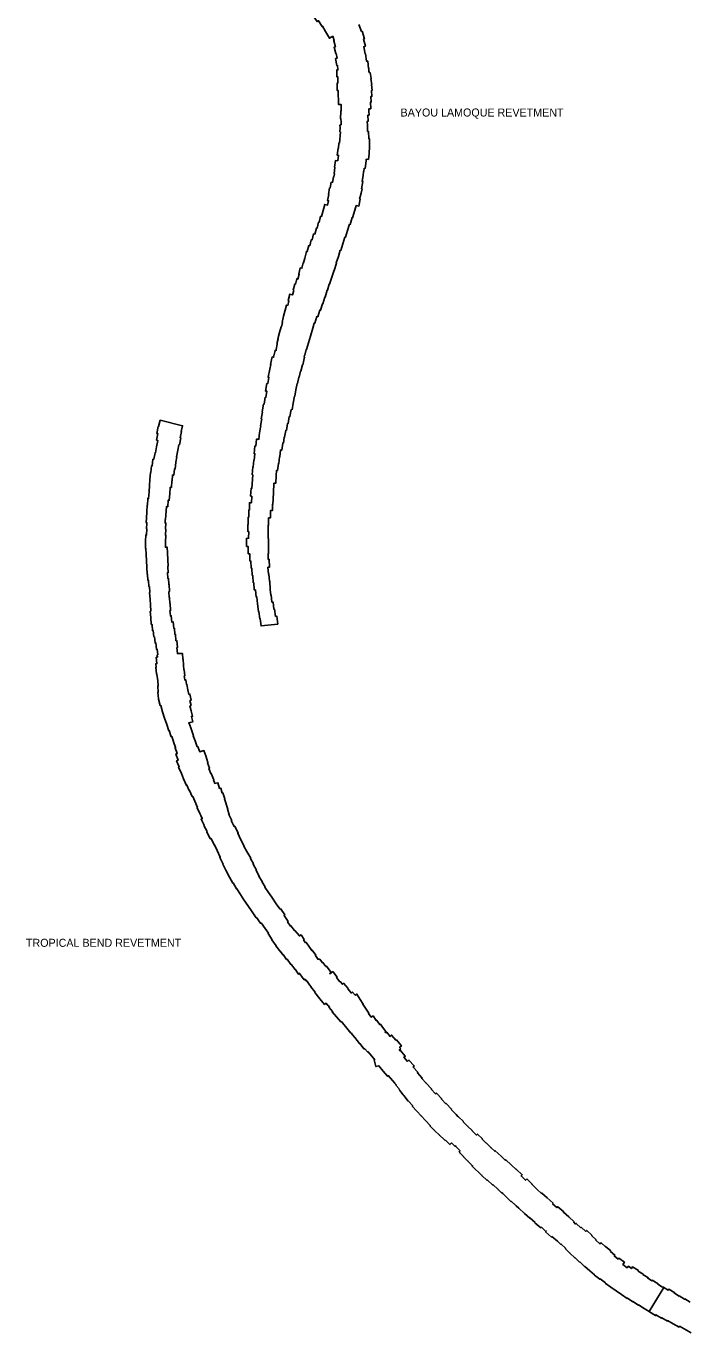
# Model space of a CAD drawing. Extents: x 2650582 to 3923188, y 277893 to 989177.
# Drawn here: x 3827116 to 3840315, y 322407 to 348533 of the extents above; entities that cross this region are included whole.
import ezdxf

# ---------------------------------------------------------------- set-up
doc = ezdxf.new("R2010")
doc.units = 0
doc.layers.add('Level 18', color=7, linetype='Continuous')
doc.layers.add('Level 3', color=7, linetype='Continuous')

msp = doc.modelspace()

# ---------------------------------------------------------------- linework, layer by layer
at = {"layer": 'Level 18'}
msp.add_lwpolyline([(3830237, 335992), (3830137, 335987)], dxfattribs=at)
at = {"layer": 'Level 3'}
for points in [[(3833239, 348329), (3833174, 348290), (3833094, 348424), (3833098, 348427), (3833037, 348530), (3833028, 348525), (3832956, 348642), (3832928, 348624), (3832849, 348742), (3832823, 348726), (3832739, 348856), (3832767, 348874), (3832711, 348962), (3832688, 348945), (3832596, 349073), (3832625, 349094)], [(3833765, 348565), (3833817, 348428), (3833825, 348431), (3833874, 348280), (3833855, 348273), (3833893, 348131), (3833861, 348122), (3833891, 347980), (3833893, 347980), (3833916, 347831), (3833941, 347833), (3833956, 347688), (3833962, 347689), (3833964, 347633), (3833972, 347602), (3833986, 347604), (3834009, 347483), (3834002, 347481), (3834021, 347365), (3834013, 347363), (3834025, 347246), (3834014, 347245), (3834023, 347127), (3834003, 347126), (3834010, 347017), (3833996, 347016), (3834001, 346882), (3833964, 346880), (3833964, 346832), (3833967, 346755), (3833943, 346755), (3833947, 346630), (3833931, 346629), (3833934, 346554), (3833935, 346427)], [(3833411, 346559), (3833410, 346611), (3833406, 346611), (3833403, 346680), (3833397, 346680), (3833400, 346835), (3833408, 346835), (3833409, 346965), (3833356, 346964), (3833351, 347245), (3833330, 347245), (3833331, 347398), (3833343, 347399), (3833343, 347516), (3833325, 347516), (3833319, 347657), (3833343, 347658), (3833333, 347750), (3833320, 347749), (3833298, 347885), (3833327, 347891), (3833307, 347989), (3833300, 347988), (3833267, 348112), (3833295, 348122), (3833259, 348241), (3833270, 348246), (3833239, 348329)], [(3833935, 346427), (3833952, 346427), (3833960, 346282), (3833973, 346281), (3833973, 346135), (3833978, 346134), (3833969, 345980), (3833968, 345980), (3833952, 345867), (3833908, 345873), (3833905, 345842), (3833910, 345841), (3833887, 345688), (3833869, 345690), (3833860, 345627), (3833858, 345628), (3833846, 345548), (3833827, 345430), (3833839, 345427), (3833817, 345281), (3833826, 345280), (3833807, 345195), (3833810, 345193), (3833776, 345074), (3833787, 345072), (3833762, 344934), (3833710, 344944), (3833683, 344855), (3833634, 344703), (3833631, 344704), (3833589, 344570), (3833576, 344573), (3833537, 344447), (3833534, 344448), (3833494, 344313), (3833484, 344315), (3833442, 344181), (3833440, 344181), (3833401, 344049), (3833391, 344051), (3833353, 343926), (3833310, 343798), (3833315, 343796), (3833272, 343650), (3833266, 343651)], [(3833267, 345585), (3833285, 345708), (3833278, 345710), (3833298, 345848), (3833339, 345842), (3833354, 345951), (3833328, 345955), (3833347, 346093), (3833354, 346093), (3833363, 346194), (3833374, 346194), (3833394, 346419), (3833383, 346420), (3833387, 346506), (3833384, 346554), (3833390, 346554), (3833390, 346560), (3833411, 346559)], [(3832107, 342044), (3832113, 342070), (3832107, 342071), (3832133, 342176), (3832125, 342178), (3832150, 342279), (3832142, 342281), (3832174, 342405), (3832175, 342405), (3832209, 342522), (3832216, 342520), (3832240, 342606), (3832229, 342609), (3832260, 342733), (3832291, 342854), (3832320, 342955), (3832341, 342950), (3832363, 343041), (3832349, 343045), (3832381, 343173), (3832438, 343159), (3832461, 343250), (3832450, 343253), (3832481, 343377), (3832494, 343374), (3832521, 343483), (3832546, 343477), (3832570, 343572), (3832561, 343574), (3832593, 343699), (3832623, 343691), (3832651, 343802), (3832659, 343799), (3832680, 343894), (3832714, 344030), (3832731, 344026), (3832761, 344147), (3832781, 344142), (3832812, 344263), (3832828, 344259), (3832858, 344380), (3832884, 344374), (3832914, 344495), (3832926, 344492), (3832956, 344614), (3832969, 344610), (3832999, 344732), (3833018, 344727), (3833048, 344848), (3833081, 344969), (3833136, 344955), (3833156, 345041), (3833139, 345045), (3833161, 345167), (3833155, 345168), (3833178, 345298), (3833187, 345297), (3833207, 345412), (3833236, 345407), (3833256, 345520), (3833265, 345519), (3833276, 345583), (3833267, 345585)], [(3833266, 343651), (3833223, 343512), (3833221, 343513), (3833179, 343375), (3833171, 343377), (3833133, 343254), (3833130, 343254), (3833088, 343116), (3833082, 343117), (3833043, 342983), (3833038, 342984), (3832999, 342851), (3832982, 342855), (3832941, 342722), (3832922, 342727), (3832881, 342594), (3832870, 342596), (3832841, 342495), (3832843, 342494), (3832793, 342334), (3832796, 342334), (3832758, 342203), (3832754, 342204), (3832715, 342069), (3832710, 342069), (3832682, 341953), (3832676, 341954), (3832668, 341917)], [(3831836, 340817), (3831829, 340819), (3831855, 340974), (3831869, 340972), (3831891, 341112), (3831906, 341110), (3831927, 341233), (3831899, 341238), (3831924, 341390), (3831942, 341387), (3831965, 341510), (3831949, 341513), (3831983, 341672), (3832005, 341770), (3831999, 341771), (3832032, 341919), (3832057, 341913), (3832088, 342048), (3832107, 342044)], [(3832668, 341917), (3832675, 341915), (3832642, 341762), (3832634, 341763), (3832604, 341632), (3832596, 341633), (3832567, 341514), (3832562, 341515), (3832535, 341388), (3832531, 341388), (3832506, 341261), (3832504, 341261), (3832482, 341132), (3832477, 341133), (3832452, 340992), (3832449, 340993), (3832427, 340863)], [(3831515, 338131), (3831516, 338292), (3831560, 338293), (3831561, 338428), (3831547, 338429), (3831546, 338566), (3831550, 338566), (3831550, 338714), (3831562, 338714), (3831561, 338858), (3831577, 338858), (3831577, 339005), (3831617, 339005), (3831623, 339135), (3831599, 339138), (3831608, 339293), (3831627, 339292), (3831643, 339563), (3831632, 339564), (3831645, 339720), (3831653, 339719), (3831666, 339858), (3831673, 339857), (3831686, 339983), (3831668, 339985), (3831685, 340139), (3831702, 340137), (3831719, 340278), (3831764, 340273), (3831779, 340399), (3831776, 340401), (3831802, 340540), (3831798, 340541), (3831823, 340681), (3831812, 340683), (3831836, 340817)], [(3832427, 340863), (3832411, 340865), (3832386, 340726), (3832373, 340728), (3832348, 340588), (3832337, 340590), (3832314, 340449), (3832301, 340450), (3832279, 340313), (3832270, 340313), (3832256, 340197), (3832242, 340198), (3832225, 340058), (3832198, 340060), (3832181, 339922), (3832177, 339922), (3832162, 339788), (3832154, 339789), (3832137, 339651), (3832119, 339651), (3832111, 339546), (3832113, 339546), (3832102, 339395), (3832065, 339395), (3832056, 339200), (3832045, 338970), (3832036, 338970), (3832035, 338847), (3831997, 338846), (3831997, 338701), (3831958, 338701), (3831959, 338555), (3831949, 338554), (3831949, 338434), (3831953, 338433), (3831951, 338289), (3831960, 338288)], [(3829894, 338669), (3829902, 338669), (3829918, 338927), (3829944, 338925), (3829952, 339055), (3829975, 339054), (3829983, 339184), (3829984, 339184), (3829993, 339313), (3830016, 339312), (3830025, 339441), (3830031, 339440), (3830038, 339558), (3830065, 339556), (3830077, 339678), (3830090, 339676), (3830107, 339816), (3830104, 339816), (3830124, 339925), (3830122, 339925), (3830146, 340053), (3830144, 340054), (3830167, 340165), (3830178, 340163), (3830206, 340301), (3830193, 340304), (3830220, 340427), (3830212, 340429), (3830241, 340542), (3829794, 340654), (3829762, 340527), (3829756, 340528), (3829726, 340391), (3829748, 340386), (3829721, 340256), (3829745, 340251), (3829720, 340125), (3829722, 340125), (3829700, 340003), (3829690, 340005), (3829666, 339872), (3829649, 339874), (3829632, 339738), (3829618, 339739), (3829606, 339607), (3829597, 339608), (3829589, 339468), (3829589, 339468), (3829581, 339349), (3829580, 339349), (3829572, 339219), (3829571, 339219), (3829563, 339087), (3829545, 339089), (3829537, 338958), (3829535, 338958), (3829526, 338822), (3829527, 338822), (3829519, 338693), (3829520, 338693)], [(3829520, 338693), (3829515, 338606), (3829527, 338605), (3829520, 338481), (3829526, 338480), (3829520, 338362), (3829505, 338362), (3829503, 338231), (3829497, 338231), (3829499, 338092), (3829509, 338092), (3829511, 337968), (3829512, 337969), (3829521, 337842), (3829518, 337841), (3829527, 337713), (3829527, 337713), (3829536, 337575), (3829540, 337575), (3829549, 337452), (3829561, 337452), (3829569, 337329), (3829578, 337329), (3829587, 337210), (3829582, 337210), (3829592, 337072), (3829594, 337072), (3829602, 336960), (3829597, 336960), (3829606, 336836), (3829595, 336835), (3829604, 336708), (3829604, 336708), (3829616, 336571), (3829630, 336572), (3829641, 336446), (3829656, 336448), (3829667, 336322)], [(3830096, 336374), (3830087, 336373), (3830076, 336496), (3830064, 336495), (3830053, 336621), (3830025, 336618), (3830014, 336744), (3829996, 336742), (3829988, 336849), (3830002, 336849), (3829992, 336988), (3829989, 336987), (3829980, 337111), (3829974, 337110), (3829966, 337229), (3829982, 337230), (3829973, 337367), (3829965, 337367), (3829956, 337494), (3829945, 337493), (3829937, 337603), (3829952, 337604), (3829943, 337732), (3829952, 337733), (3829943, 337863), (3829946, 337863), (3829936, 338001), (3829934, 338114), (3829898, 338114), (3829897, 338217), (3829902, 338217), (3829904, 338355), (3829898, 338355), (3829904, 338473), (3829901, 338473), (3829908, 338599), (3829890, 338600), (3829894, 338669)], [(3831960, 338288), (3831959, 337986), (3831953, 337986), (3831953, 337871), (3831971, 337871), (3831980, 337716), (3831947, 337713), (3831955, 337577), (3831966, 337578), (3831975, 337435), (3831981, 337435), (3831991, 337269), (3832002, 337159), (3832009, 337160), (3832026, 337017), (3832047, 337018), (3832064, 336873), (3832080, 336874), (3832097, 336730), (3832125, 336733), (3832143, 336577), (3831809, 336540), (3831792, 336686), (3831783, 336685), (3831766, 336829), (3831755, 336828), (3831737, 336984), (3831740, 336984), (3831724, 337119), (3831711, 337118), (3831697, 337261), (3831673, 337261), (3831663, 337405), (3831652, 337405), (3831644, 337550), (3831632, 337550), (3831625, 337693), (3831611, 337693), (3831603, 337840), (3831583, 337839), (3831581, 337985), (3831551, 337985), (3831549, 338130), (3831515, 338131)], [(3829667, 336322), (3829679, 336323), (3829690, 336200), (3829707, 336202), (3829718, 336074), (3829733, 336075), (3829743, 335964), (3829735, 335963), (3829739, 335917), (3829715, 335915), (3829729, 335789), (3829707, 335786), (3829715, 335715), (3829708, 335714), (3829720, 335577), (3829729, 335578), (3829743, 335445), (3829743, 335445), (3829754, 335342), (3829743, 335340), (3829756, 335215), (3829747, 335214), (3829761, 335082), (3829761, 335082), (3829761, 335082), (3829762, 335077), (3829762, 335077), (3829794, 334949), (3829804, 334951), (3829841, 334826), (3829837, 334825), (3829881, 334699), (3829880, 334699), (3829925, 334568), (3829927, 334568), (3829969, 334447), (3829973, 334449), (3830015, 334327), (3830025, 334331), (3830061, 334228), (3830060, 334227), (3830101, 334109), (3830092, 334106), (3830133, 333988), (3830108, 333980), (3830151, 333854), (3830120, 333841), (3830170, 333724), (3830161, 333720), (3830216, 333590), (3830217, 333590), (3830262, 333484), (3830317, 333354)], [(3831113, 332981), (3831081, 333085), (3831083, 333086), (3831046, 333204), (3831032, 333200), (3831003, 333299), (3830976, 333291), (3830945, 333407), (3830888, 333392), (3830861, 333462), (3830863, 333463), (3830812, 333593), (3830807, 333591), (3830767, 333694), (3830780, 333699), (3830739, 333806), (3830747, 333809), (3830702, 333941), (3830702, 333941), (3830668, 334050), (3830585, 334025), (3830580, 334036), (3830576, 334034), (3830543, 334129), (3830534, 334127), (3830494, 334244), (3830489, 334243), (3830454, 334345), (3830457, 334346), (3830416, 334465), (3830416, 334465), (3830371, 334597), (3830364, 334595), (3830361, 334602), (3830446, 334625), (3830418, 334731), (3830441, 334737), (3830412, 334842), (3830415, 334842), (3830387, 334946), (3830412, 334952), (3830387, 335051), (3830415, 335057), (3830387, 335178), (3830366, 335173), (3830347, 335262), (3830326, 335371), (3830320, 335369), (3830305, 335465), (3830284, 335462), (3830274, 335542), (3830283, 335543), (3830270, 335666), (3830265, 335665), (3830257, 335755), (3830258, 335755), (3830249, 335879), (3830243, 335879), (3830237, 335992), (3830137, 335987), (3830126, 336109), (3830142, 336111), (3830129, 336248), (3830107, 336246), (3830096, 336374)], [(3830317, 333354), (3830326, 333358), (3830372, 333249), (3830378, 333252), (3830431, 333131), (3830439, 333135), (3830441, 333127), (3830446, 333128), (3830485, 333039), (3830483, 333038), (3830538, 332912), (3830529, 332907), (3830585, 332791), (3830584, 332791), (3830603, 332754), (3830629, 332693), (3830633, 332695), (3830637, 332688), (3830610, 332675), (3830669, 332555), (3830668, 332554), (3830730, 332428), (3830727, 332426), (3830795, 332286), (3830810, 332293), (3830873, 332164), (3830875, 332166), (3830931, 332051), (3830929, 332050), (3830994, 331917), (3830982, 331911), (3831050, 331780), (3831045, 331777), (3831107, 331661), (3831102, 331659), (3831178, 331520), (3831179, 331521), (3831244, 331400), (3831250, 331404), (3831319, 331282), (3831327, 331287), (3831395, 331169), (3831397, 331170), (3831464, 331068), (3831464, 331067), (3831542, 330953), (3831541, 330953), (3831631, 330823), (3831632, 330823), (3831711, 330708)], [(3832194, 330893), (3832181, 330884), (3832112, 330984), (3832113, 330985), (3832023, 331115), (3832022, 331115), (3831954, 331214), (3831955, 331214), (3831882, 331319), (3831889, 331324), (3831829, 331416), (3831834, 331418), (3831766, 331537), (3831773, 331541), (3831709, 331654), (3831716, 331658), (3831650, 331778), (3831657, 331782), (3831596, 331893), (3831601, 331895), (3831526, 332034), (3831522, 332032), (3831467, 332140), (3831468, 332140), (3831399, 332281), (3831398, 332281), (3831342, 332395), (3831353, 332400), (3831284, 332541), (3831270, 332534), (3831214, 332648), (3831224, 332653), (3831167, 332770), (3831173, 332771), (3831141, 332876), (3831143, 332876), (3831111, 332980), (3831113, 332981)], [(3833242, 329629), (3833185, 329585), (3833182, 329589), (3833212, 329612), (3833115, 329740), (3833105, 329732), (3833045, 329811), (3833036, 329805), (3832981, 329882), (3832969, 329874), (3832962, 329884), (3832946, 329873), (3832893, 329949), (3832902, 329956), (3832831, 330058), (3832822, 330051), (3832764, 330138), (3832763, 330138), (3832711, 330215), (3832698, 330206), (3832657, 330268), (3832667, 330274), (3832608, 330365), (3832574, 330342), (3832480, 330455), (3832476, 330451), (3832404, 330547), (3832395, 330540), (3832339, 330626), (3832348, 330632), (3832269, 330753), (3832283, 330763), (3832194, 330893)], [(3831711, 330708), (3831716, 330711), (3831796, 330596), (3831809, 330605), (3831888, 330490), (3831893, 330494), (3831957, 330396), (3831948, 330390), (3832028, 330268), (3832024, 330264), (3832110, 330148), (3832102, 330142), (3832202, 330021), (3832203, 330022), (3832241, 329966), (3832248, 329971), (3832265, 329951), (3832320, 329869), (3832331, 329876), (3832401, 329773), (3832408, 329778), (3832422, 329758), (3832425, 329761), (3832481, 329678), (3832487, 329681), (3832557, 329578), (3832578, 329593), (3832586, 329583), (3832627, 329518), (3832631, 329521), (3832671, 329464), (3832689, 329477), (3832715, 329439), (3832720, 329443), (3832777, 329364), (3832779, 329365), (3832807, 329328), (3832804, 329326), (3832887, 329216), (3832883, 329213), (3832980, 329085), (3832981, 329086), (3833078, 328973), (3833106, 328997), (3833144, 328952), (3833148, 328955), (3833175, 328922), (3833166, 328914), (3833238, 328833), (3833230, 328827), (3833405, 328624), (3833413, 328631), (3833436, 328603), (3833435, 328603), (3833524, 328496), (3833525, 328496), (3833604, 328401), (3833607, 328404), (3833636, 328369)], [(3834599, 328088), (3834576, 328115), (3834612, 328145), (3834512, 328264), (3834502, 328256), (3834416, 328361), (3834383, 328334), (3834379, 328339), (3834378, 328338), (3834318, 328418), (3834303, 328406), (3834289, 328425), (3834302, 328435), (3834235, 328517), (3834192, 328580), (3834178, 328570), (3834117, 328660), (3834107, 328653), (3834046, 328744), (3834009, 328719), (3833958, 328794), (3833962, 328797), (3833895, 328901), (3833892, 328899), (3833841, 328978), (3833846, 328981), (3833786, 329072), (3833790, 329075), (3833722, 329179), (3833689, 329157), (3833637, 329222), (3833612, 329202), (3833544, 329287), (3833546, 329289), (3833456, 329396), (3833433, 329377), (3833391, 329429), (3833385, 329424), (3833317, 329509), (3833328, 329519), (3833242, 329629)], [(3833636, 328369), (3833680, 328313), (3833775, 328191), (3833779, 328193), (3833871, 328081), (3833880, 328088), (3833933, 328026), (3833940, 328032), (3833979, 327985), (3833982, 327987), (3834023, 327938), (3834023, 327938), (3834081, 327869), (3834068, 327865), (3834103, 327732), (3834161, 327747), (3834159, 327745), (3834248, 327638), (3834249, 327639), (3834333, 327538), (3834349, 327551), (3834431, 327452), (3834432, 327453), (3834479, 327397), (3834478, 327396), (3834499, 327373), (3834509, 327362), (3834504, 327358), (3834565, 327284), (3834561, 327281), (3834584, 327257), (3834579, 327253), (3834650, 327168), (3834649, 327167), (3834662, 327154), (3834658, 327150), (3834747, 327043), (3834750, 327045), (3834839, 326946), (3834830, 326938), (3834920, 326843), (3834918, 326841), (3835007, 326748), (3835006, 326746), (3835095, 326652), (3835094, 326650), (3835187, 326552), (3835182, 326547), (3835274, 326456), (3835274, 326456), (3835372, 326359), (3835376, 326363), (3835468, 326272), (3835469, 326273)], [(3835749, 326725), (3835703, 326773), (3835704, 326774), (3835608, 326875), (3835614, 326881), (3835506, 326996), (3835498, 326988), (3835412, 327080), (3835418, 327085), (3835310, 327200), (3835296, 327187), (3835209, 327279), (3835215, 327285), (3835107, 327400), (3835105, 327399), (3835017, 327492), (3835028, 327502), (3834931, 327605), (3834943, 327617), (3834844, 327722), (3834868, 327745), (3834761, 327860), (3834734, 327835), (3834663, 327918), (3834688, 327939), (3834585, 328059), (3834578, 328052), (3834569, 328062), (3834599, 328088)], [(3837116, 325484), (3837093, 325460), (3837003, 325546), (3837025, 325568), (3836912, 325676), (3836906, 325671), (3836803, 325770), (3836802, 325769), (3836696, 325870), (3836686, 325858), (3836602, 325938), (3836603, 325939), (3836488, 326049), (3836476, 326037), (3836404, 326106), (3836406, 326109), (3836306, 326205), (3836304, 326203), (3836223, 326280), (3836230, 326287), (3836130, 326383), (3836111, 326363), (3836024, 326447), (3836027, 326451), (3835934, 326541), (3835935, 326542), (3835847, 326627), (3835850, 326630), (3835750, 326726), (3835749, 326725)], [(3835469, 326273), (3835489, 326254), (3835493, 326258), (3835581, 326173), (3835611, 326205), (3835683, 326134), (3835696, 326148), (3835700, 326143), (3835695, 326138), (3835784, 326050), (3835764, 326030), (3835785, 326010), (3835779, 326004), (3835853, 325932), (3835850, 325930), (3835940, 325842), (3835940, 325841), (3836034, 325750), (3836025, 325741), (3836218, 325553), (3836219, 325554), (3836324, 325454), (3836332, 325462), (3836433, 325366), (3836439, 325372), (3836544, 325272), (3836546, 325275), (3836613, 325209), (3836615, 325211), (3836636, 325191), (3836636, 325191), (3836749, 325082)], [(3838064, 324630), (3837954, 324724), (3837956, 324726), (3837848, 324819), (3837855, 324828), (3837736, 324930), (3837720, 324912), (3837631, 324988), (3837643, 325001), (3837526, 325107), (3837524, 325104), (3837417, 325201), (3837411, 325195), (3837326, 325271), (3837327, 325273), (3837224, 325372), (3837228, 325376), (3837116, 325484)], [(3836749, 325082), (3836750, 325083), (3836805, 325029), (3836810, 325034), (3836857, 324989), (3836859, 324991), (3836906, 324945), (3836908, 324948), (3836958, 324901), (3836957, 324900), (3837074, 324795), (3837074, 324795), (3837177, 324702), (3837180, 324705), (3837282, 324612), (3837280, 324610), (3837399, 324508), (3837409, 324520), (3837498, 324434), (3837506, 324442), (3837507, 324441), (3837493, 324425), (3837612, 324323), (3837619, 324332), (3837729, 324238), (3837732, 324241)], [(3839858, 323313), (3839835, 323327), (3839831, 323322), (3839738, 323380), (3839741, 323386), (3839623, 323460), (3839617, 323450), (3839530, 323505), (3839537, 323515), (3839438, 323577), (3839440, 323581), (3839341, 323643), (3839347, 323653), (3839228, 323727), (3839207, 323693), (3839146, 323739), (3839124, 323710), (3839036, 323777), (3839068, 323818), (3838956, 323902), (3838940, 323882), (3838863, 323946), (3838878, 323964), (3838787, 324037), (3838795, 324045), (3838689, 324137), (3838685, 324132), (3838600, 324210), (3838577, 324186), (3838496, 324261), (3838503, 324267), (3838411, 324352), (3838417, 324358), (3838314, 324454), (3838296, 324434), (3838204, 324519), (3838196, 324509), (3838104, 324595), (3838092, 324582), (3838054, 324618), (3838064, 324630)], [(3837732, 324241), (3837799, 324176), (3837805, 324182), (3837892, 324098), (3837887, 324094), (3837980, 324003), (3837979, 324002), (3838078, 323906), (3838082, 323910), (3838173, 323821), (3838176, 323825), (3838272, 323732), (3838277, 323737), (3838378, 323649), (3838472, 323566), (3838471, 323564), (3838579, 323478), (3838585, 323485), (3838689, 323407), (3838686, 323403), (3838797, 323321), (3838798, 323322), (3838903, 323251), (3838902, 323249), (3839010, 323176), (3839008, 323172), (3839122, 323095), (3839127, 323102), (3839234, 323029), (3839237, 323034), (3839346, 322964), (3839348, 322966), (3839460, 322894), (3839462, 322897), (3839564, 322836), (3839858, 323313)], [(3840401, 322407), (3840169, 322540), (3840159, 322522), (3840044, 322591), (3840041, 322585), (3839930, 322652), (3839925, 322644), (3839814, 322711), (3839808, 322701), (3839697, 322768), (3839689, 322754), (3839568, 322827), (3839571, 322832), (3839564, 322836), (3839858, 323313), (3839941, 323261), (3839953, 323281), (3840072, 323206), (3840068, 323201), (3840161, 323142), (3840163, 323146), (3840269, 323080), (3840274, 323086), (3840380, 323020)]]:
    msp.add_lwpolyline(points, dxfattribs=at)

# ---------------------------------------------------------------- texts
for s, p in [('BAYOU LAMOQUE REVETMENT', (3834595, 346726)), ('TROPICAL BEND REVETMENT', (3827111, 330126))]:
    msp.add_text(s, height=160, dxfattribs=at).set_placement(p)

doc.saveas('drawing.dxf')
